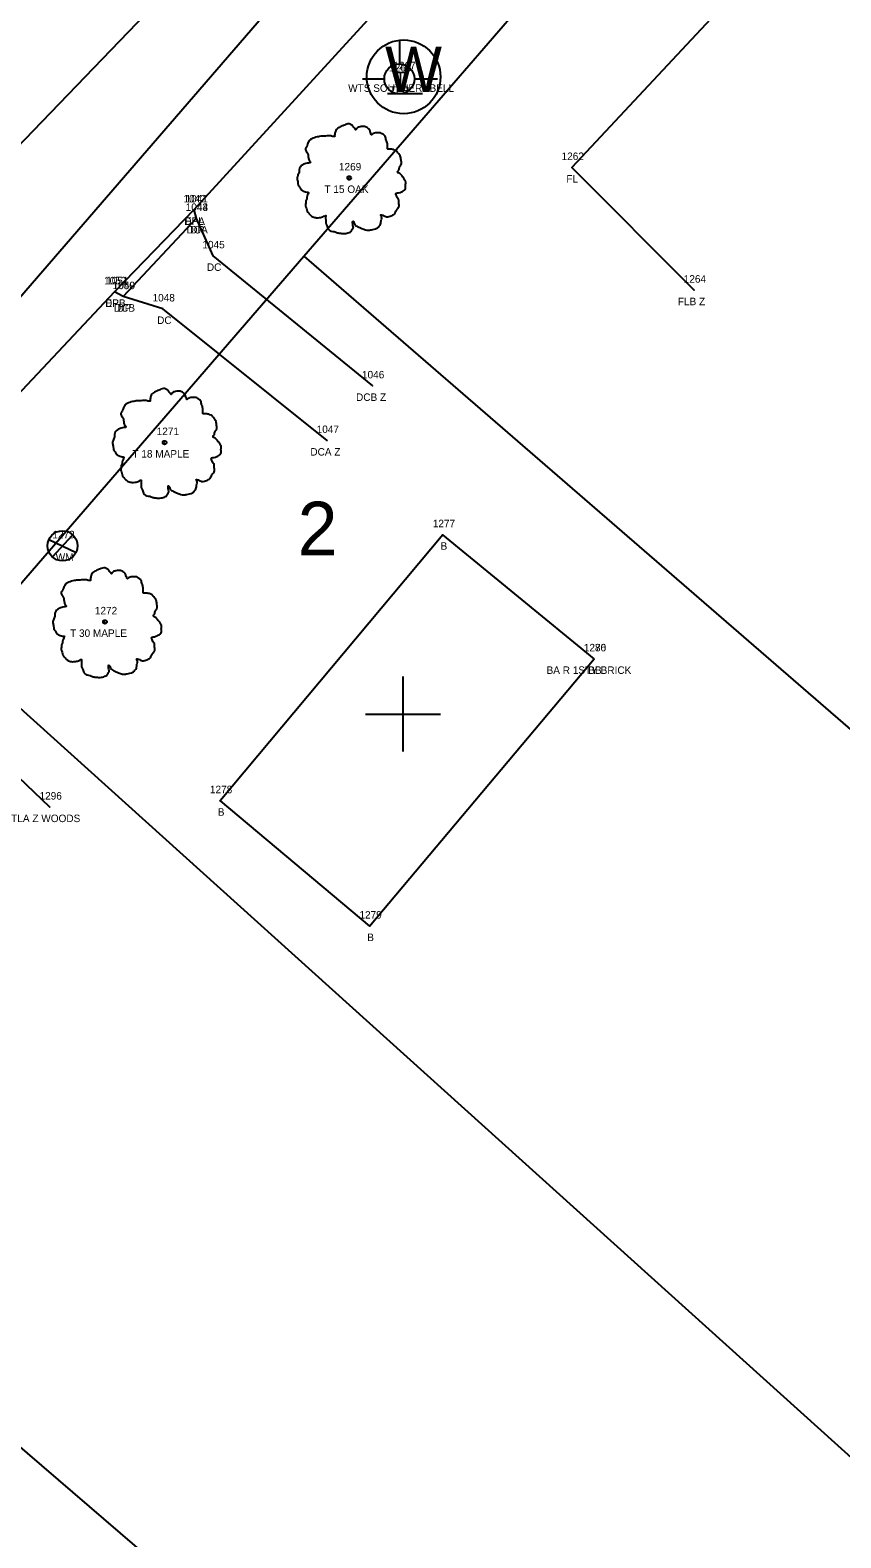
# Model space of a CAD drawing. Extents: x 1812113 to 1819860, y 1177395 to 1181185.
# Drawn here: x 1813877.7 to 1813985.7, y 1178074.8 to 1178275.6 of the extents above; entities that cross this region are included whole.
import ezdxf

# ---------------------------------------------------------------- set-up
doc = ezdxf.new("R2010")
doc.units = 0
for name, color, linetype in [('RD_EX_Bldg', 7, 'Continuous'), ('RD_EX_Bldg_txCode', 7, 'Continuous'), ('RD_EX_Conc', 7, 'Continuous'), ('RD_EX_Conc_txCode', 7, 'Continuous'), ('RD_EX_Driveway', 7, 'Continuous'), ('RD_EX_Driveway_txCode', 7, 'Continuous'), ('RD_EX_DV_Prop', 7, 'Continuous'), ('RD_EX_DV_TX_Prop', 7, 'Continuous'), ('RD_EX_Fence_Other', 7, 'Continuous'), ('RD_EX_Fence_Other_txCode', 7, 'Continuous'), ('RD_EX_Misc', 7, 'Continuous'), ('RD_EX_Road', 7, 'Continuous'), ('RD_EX_Road_txCode', 7, 'Continuous'), ('RD_EX_UT', 7, 'Continuous'), ('RD_EX_UT_txCode', 7, 'Continuous'), ('RD_EX_VEG', 7, 'Continuous'), ('RD_EX_VEG_txCode', 7, 'Continuous'), ('RD_HC_CL', 7, 'Continuous'), ('RD_SMD_Locator', 7, 'Continuous')]:
    doc.layers.add(name, color=color, linetype=linetype)

msp = doc.modelspace()

# ---------------------------------------------------------------- linework, layer by layer
at = {"layer": 'RD_EX_Bldg'}
msp.add_lwpolyline([(1813952.83, 1178191.89), (1813932.67, 1178208.43), (1813902.97, 1178173), (1813922.9, 1178156.3), (1813952.83, 1178191.89)], dxfattribs=at)
at = {"layer": 'RD_EX_Conc'}
for points in [[(1813899.79, 1178250.56), (1813902, 1178245.57), (1813923.3, 1178228.25)], [(1813917.24, 1178220.97), (1813895.37, 1178238.5), (1813890.08, 1178240.14)]]:
    msp.add_lwpolyline(points, dxfattribs=at)
at = {"layer": 'RD_EX_Driveway'}
msp.add_lwpolyline([(1813899.48, 1178251.69), (1813899.79, 1178250.56), (1813890.08, 1178240.14), (1813888.9, 1178240.78)], dxfattribs=at)
at = {"layer": 'RD_EX_DV_Prop'}
for p, q in [((1813914.12, 1178245.52), (1814044.97, 1178396.77)), ((1813868.31, 1178192.56), (1813914.12, 1178245.52)), ((1813914.12, 1178245.52), (1814088.82, 1178094.39)), ((1813868.31, 1178192.56), (1814033.95, 1178043.26)), ((1813819.24, 1178135.84), (1813982.43, 1177995.87))]:
    msp.add_line(p, q, dxfattribs=at)
at = {"layer": 'RD_EX_Fence_Other'}
msp.add_lwpolyline([(1814039.17, 1178321.6), (1814032.91, 1178334.96), (1814018.04, 1178330.3), (1813949.86, 1178257.34), (1813966.14, 1178241)], dxfattribs=at)
at = {"layer": 'RD_EX_Misc'}
for p, q in [((1813927.36, 1178179.54), (1813927.36, 1178189.54)), ((1813922.36, 1178184.54), (1813932.36, 1178184.54))]:
    msp.add_line(p, q, dxfattribs=at)
at = {"layer": 'RD_EX_Road'}
for p, q in [((1813874.69, 1178258.74), (1813910.02, 1178295.38)), ((1813927.09, 1178281.88), (1813899.48, 1178251.69)), ((1813899.48, 1178251.69), (1813888.9, 1178240.78)), ((1813888.9, 1178240.78), (1813846.63, 1178195.79))]:
    msp.add_line(p, q, dxfattribs=at)
at = {"layer": 'RD_EX_UT'}
for p, q in [((1813926.87, 1178274.22), (1813926.87, 1178271.15)), ((1813921.94, 1178269.17), (1813924.87, 1178269.17)), ((1813928.87, 1178269.17), (1813931.94, 1178269.17)), ((1813925.31, 1178267.21), (1813929.94, 1178267.21)), ((1813880.63, 1178205.49), (1813883.29, 1178208.39)), ((1813880.15, 1178207.79), (1813883.78, 1178206.07))]:
    msp.add_line(p, q, dxfattribs=at)
for centre, radius in [((1813927.44, 1178269.42), 4.91), ((1813926.87, 1178269.15), 2), ((1813881.98, 1178206.95), 2)]:
    msp.add_circle(centre, radius, dxfattribs=at)
at = {"layer": 'RD_EX_VEG'}
msp.add_lwpolyline([(1813880.29, 1178172.15), (1813856.42, 1178194.9), (1813848.45, 1178185.53)], dxfattribs=at)
for centre, radius in [((1813920.19, 1178255.95), 0.25), ((1813920.17, 1178255.94), 0.0001), ((1813895.59, 1178220.7), 0.25), ((1813895.58, 1178220.69), 0.0001), ((1813887.64, 1178196.82), 0.25), ((1813887.63, 1178196.81), 0.0001)]:
    msp.add_circle(centre, radius, dxfattribs=at)
for points in [[(1813920.32, 1178263.12), (1813920.02, 1178263.15), (1813919.69, 1178263.05), (1813919.44, 1178262.95), (1813919.22, 1178262.87), (1813918.99, 1178262.77), (1813918.69, 1178262.6), (1813918.47, 1178262.4), (1813918.34, 1178262.15), (1813918.29, 1178261.92), (1813918.24, 1178261.65), (1813918.24, 1178261.47), (1813918.12, 1178261.45), (1813917.97, 1178261.47), (1813917.72, 1178261.55), (1813917.47, 1178261.55), (1813917.22, 1178261.55), (1813916.87, 1178261.52), (1813916.52, 1178261.52), (1813916.25, 1178261.47), (1813915.92, 1178261.42), (1813915.55, 1178261.3), (1813915.2, 1178261.17), (1813914.9, 1178260.92), (1813914.65, 1178260.45), (1813914.52, 1178260.1), (1813914.37, 1178259.85), (1813914.52, 1178259.4), (1813914.7, 1178259.05), (1813914.72, 1178258.85), (1813914.8, 1178258.42), (1813914.9, 1178258.2), (1813915.02, 1178258), (1813914.95, 1178257.97), (1813914.57, 1178257.92), (1813914.27, 1178257.82), (1813913.85, 1178257.6), (1813913.62, 1178257.37), (1813913.52, 1178257.05), (1813913.5, 1178256.7), (1813913.4, 1178256.5), (1813913.32, 1178256.22), (1813913.3, 1178256.15), (1813913.25, 1178255.82), (1813913.35, 1178255.37), (1813913.37, 1178255.02), (1813913.5, 1178254.8), (1813913.65, 1178254.63), (1813913.82, 1178254.38), (1813914.22, 1178254.15), (1813914.55, 1178254.05), (1813914.75, 1178254.03), (1813914.57, 1178253.53), (1813914.52, 1178253.18), (1813914.4, 1178252.78), (1813914.4, 1178252.7), (1813914.35, 1178252.23), (1813914.5, 1178251.9), (1813914.57, 1178251.53), (1813914.75, 1178251.3), (1813915.02, 1178251), (1813915.35, 1178250.78), (1813915.85, 1178250.65), (1813916.25, 1178250.68), (1813916.82, 1178250.85), (1813917.07, 1178250.93), (1813917.04, 1178250.75), (1813917.07, 1178250.38), (1813917.07, 1178249.95), (1813917.22, 1178249.63), (1813917.32, 1178249.35), (1813917.47, 1178249.1), (1813917.79, 1178248.88), (1813918.19, 1178248.8), (1813918.62, 1178248.65), (1813919.07, 1178248.58), (1813919.57, 1178248.55), (1813920.17, 1178248.7), (1813920.44, 1178248.83), (1813920.54, 1178249), (1813920.74, 1178249.38), (1813920.69, 1178249.6), (1813920.72, 1178250.2), (1813920.82, 1178250.03), (1813920.99, 1178249.68), (1813921.49, 1178249.38), (1813921.89, 1178249.2), (1813922.37, 1178249.05), (1813922.67, 1178248.98), (1813923.14, 1178249.05), (1813923.52, 1178249.13), (1813923.89, 1178249.25), (1813924.19, 1178249.53), (1813924.37, 1178249.8), (1813924.42, 1178250.08), (1813924.49, 1178250.45), (1813924.54, 1178250.63)], [(1813924.54, 1178250.63), (1813924.47, 1178250.8), (1813924.42, 1178251.05), (1813924.49, 1178251.03), (1813924.67, 1178250.98), (1813924.94, 1178250.85), (1813925.17, 1178250.78), (1813925.49, 1178250.8), (1813925.77, 1178250.9), (1813926.22, 1178251.18), (1813926.49, 1178251.65), (1813926.77, 1178252.05), (1813926.84, 1178252.38), (1813926.79, 1178252.6), (1813926.77, 1178253.1), (1813926.57, 1178253.35), (1813926.52, 1178253.48), (1813926.42, 1178253.88), (1813926.49, 1178253.93), (1813926.77, 1178253.98), (1813927.14, 1178254.1), (1813927.42, 1178254.23), (1813927.64, 1178254.4), (1813927.71, 1178254.63), (1813927.69, 1178255.02), (1813927.74, 1178255.42), (1813927.67, 1178255.57), (1813927.57, 1178255.72), (1813927.49, 1178255.92), (1813927.34, 1178256.07), (1813927.24, 1178256.22), (1813927.14, 1178256.32), (1813927.02, 1178256.47), (1813926.84, 1178256.6), (1813926.69, 1178256.65), (1813926.64, 1178256.8), (1813926.79, 1178257), (1813926.84, 1178257.1), (1813926.87, 1178257.32), (1813927.09, 1178257.67), (1813927.14, 1178258.07), (1813927.09, 1178258.5), (1813927.04, 1178258.77), (1813926.89, 1178259.05), (1813926.69, 1178259.3), (1813926.57, 1178259.47), (1813926.39, 1178259.6), (1813926.07, 1178259.72), (1813925.82, 1178259.77), (1813925.47, 1178259.77), (1813925.27, 1178259.82), (1813925.29, 1178259.87), (1813925.29, 1178260.02), (1813925.29, 1178260.3), (1813925.22, 1178260.75), (1813925.07, 1178261.25), (1813925.07, 1178261.27), (1813924.97, 1178261.52), (1813924.74, 1178261.72), (1813924.57, 1178261.82), (1813924.37, 1178261.95), (1813924.12, 1178261.97), (1813923.82, 1178261.97), (1813923.54, 1178261.92), (1813923.34, 1178261.82), (1813923.17, 1178261.7), (1813923.09, 1178261.85), (1813922.99, 1178262.15), (1813922.94, 1178262.3), (1813922.79, 1178262.47), (1813922.57, 1178262.67), (1813922.12, 1178262.8), (1813921.49, 1178262.72), (1813921.19, 1178262.52), (1813921.04, 1178262.35), (1813920.99, 1178262.47), (1813920.79, 1178262.67), (1813920.69, 1178262.85), (1813920.52, 1178262.97), (1813920.37, 1178263.07), (1813920.27, 1178263.12)], [(1813895.72, 1178227.87), (1813895.42, 1178227.9), (1813895.1, 1178227.8), (1813894.85, 1178227.7), (1813894.62, 1178227.62), (1813894.4, 1178227.52), (1813894.1, 1178227.35), (1813893.87, 1178227.15), (1813893.75, 1178226.9), (1813893.7, 1178226.67), (1813893.65, 1178226.4), (1813893.65, 1178226.22), (1813893.52, 1178226.2), (1813893.37, 1178226.22), (1813893.12, 1178226.3), (1813892.87, 1178226.3), (1813892.62, 1178226.3), (1813892.27, 1178226.27), (1813891.92, 1178226.27), (1813891.65, 1178226.22), (1813891.32, 1178226.17), (1813890.95, 1178226.05), (1813890.6, 1178225.92), (1813890.3, 1178225.67), (1813890.05, 1178225.2), (1813889.92, 1178224.85), (1813889.77, 1178224.6), (1813889.92, 1178224.15), (1813890.1, 1178223.8), (1813890.12, 1178223.6), (1813890.2, 1178223.17), (1813890.3, 1178222.95), (1813890.42, 1178222.75), (1813890.35, 1178222.72), (1813889.97, 1178222.67), (1813889.67, 1178222.57), (1813889.25, 1178222.35), (1813889.02, 1178222.12), (1813888.92, 1178221.8), (1813888.9, 1178221.45), (1813888.8, 1178221.25), (1813888.72, 1178220.97), (1813888.7, 1178220.9), (1813888.65, 1178220.58), (1813888.75, 1178220.13), (1813888.77, 1178219.78), (1813888.9, 1178219.55), (1813889.05, 1178219.38), (1813889.22, 1178219.13), (1813889.62, 1178218.9), (1813889.95, 1178218.8), (1813890.15, 1178218.78), (1813889.97, 1178218.28), (1813889.92, 1178217.93), (1813889.8, 1178217.53), (1813889.8, 1178217.45), (1813889.75, 1178216.98), (1813889.9, 1178216.65), (1813889.97, 1178216.28), (1813890.15, 1178216.05), (1813890.42, 1178215.75), (1813890.75, 1178215.53), (1813891.25, 1178215.4), (1813891.65, 1178215.43), (1813892.22, 1178215.6), (1813892.47, 1178215.68), (1813892.45, 1178215.5), (1813892.47, 1178215.13), (1813892.47, 1178214.7), (1813892.62, 1178214.38), (1813892.72, 1178214.1), (1813892.87, 1178213.85), (1813893.2, 1178213.63), (1813893.6, 1178213.55), (1813894.02, 1178213.4), (1813894.47, 1178213.33), (1813894.97, 1178213.3), (1813895.57, 1178213.45), (1813895.85, 1178213.58), (1813895.95, 1178213.75), (1813896.15, 1178214.13), (1813896.1, 1178214.35), (1813896.12, 1178214.95), (1813896.22, 1178214.78), (1813896.4, 1178214.43), (1813896.9, 1178214.13), (1813897.29, 1178213.95), (1813897.77, 1178213.8), (1813898.07, 1178213.73), (1813898.54, 1178213.8), (1813898.92, 1178213.88), (1813899.29, 1178214), (1813899.59, 1178214.28), (1813899.77, 1178214.55), (1813899.82, 1178214.83), (1813899.89, 1178215.2), (1813899.94, 1178215.38)], [(1813899.94, 1178215.38), (1813899.87, 1178215.55), (1813899.82, 1178215.8), (1813899.89, 1178215.78), (1813900.07, 1178215.73), (1813900.34, 1178215.6), (1813900.57, 1178215.53), (1813900.89, 1178215.55), (1813901.17, 1178215.65), (1813901.62, 1178215.93), (1813901.89, 1178216.4), (1813902.17, 1178216.8), (1813902.24, 1178217.13), (1813902.19, 1178217.35), (1813902.17, 1178217.85), (1813901.97, 1178218.1), (1813901.92, 1178218.23), (1813901.82, 1178218.63), (1813901.89, 1178218.68), (1813902.17, 1178218.73), (1813902.54, 1178218.85), (1813902.82, 1178218.98), (1813903.04, 1178219.15), (1813903.12, 1178219.38), (1813903.09, 1178219.78), (1813903.14, 1178220.18), (1813903.07, 1178220.33), (1813902.97, 1178220.48), (1813902.89, 1178220.68), (1813902.74, 1178220.82), (1813902.64, 1178220.97), (1813902.54, 1178221.07), (1813902.42, 1178221.22), (1813902.24, 1178221.35), (1813902.09, 1178221.4), (1813902.04, 1178221.55), (1813902.19, 1178221.75), (1813902.24, 1178221.85), (1813902.27, 1178222.07), (1813902.49, 1178222.42), (1813902.54, 1178222.82), (1813902.49, 1178223.25), (1813902.44, 1178223.52), (1813902.29, 1178223.8), (1813902.09, 1178224.05), (1813901.97, 1178224.22), (1813901.79, 1178224.35), (1813901.47, 1178224.47), (1813901.22, 1178224.52), (1813900.87, 1178224.52), (1813900.67, 1178224.57), (1813900.69, 1178224.62), (1813900.69, 1178224.77), (1813900.69, 1178225.05), (1813900.62, 1178225.5), (1813900.47, 1178226), (1813900.47, 1178226.02), (1813900.37, 1178226.27), (1813900.14, 1178226.47), (1813899.97, 1178226.57), (1813899.77, 1178226.7), (1813899.52, 1178226.72), (1813899.22, 1178226.72), (1813898.94, 1178226.67), (1813898.74, 1178226.57), (1813898.57, 1178226.45), (1813898.49, 1178226.6), (1813898.39, 1178226.9), (1813898.34, 1178227.05), (1813898.19, 1178227.22), (1813897.97, 1178227.42), (1813897.52, 1178227.55), (1813896.9, 1178227.47), (1813896.6, 1178227.27), (1813896.45, 1178227.1), (1813896.4, 1178227.22), (1813896.2, 1178227.42), (1813896.1, 1178227.6), (1813895.92, 1178227.72), (1813895.77, 1178227.82), (1813895.67, 1178227.87)], [(1813887.77, 1178203.99), (1813887.47, 1178204.02), (1813887.15, 1178203.92), (1813886.9, 1178203.82), (1813886.67, 1178203.74), (1813886.45, 1178203.64), (1813886.15, 1178203.47), (1813885.92, 1178203.27), (1813885.8, 1178203.02), (1813885.75, 1178202.79), (1813885.7, 1178202.52), (1813885.7, 1178202.34), (1813885.57, 1178202.32), (1813885.42, 1178202.34), (1813885.17, 1178202.42), (1813884.92, 1178202.42), (1813884.67, 1178202.42), (1813884.32, 1178202.39), (1813883.97, 1178202.39), (1813883.7, 1178202.34), (1813883.37, 1178202.29), (1813883, 1178202.17), (1813882.65, 1178202.04), (1813882.35, 1178201.79), (1813882.1, 1178201.32), (1813881.97, 1178200.97), (1813881.82, 1178200.72), (1813881.97, 1178200.27), (1813882.15, 1178199.92), (1813882.17, 1178199.72), (1813882.25, 1178199.29), (1813882.35, 1178199.07), (1813882.47, 1178198.87), (1813882.4, 1178198.84), (1813882.02, 1178198.79), (1813881.72, 1178198.69), (1813881.3, 1178198.47), (1813881.07, 1178198.24), (1813880.97, 1178197.92), (1813880.95, 1178197.57), (1813880.85, 1178197.37), (1813880.77, 1178197.09), (1813880.75, 1178197.02), (1813880.7, 1178196.69), (1813880.8, 1178196.24), (1813880.82, 1178195.89), (1813880.95, 1178195.67), (1813881.1, 1178195.5), (1813881.27, 1178195.25), (1813881.67, 1178195.02), (1813882, 1178194.92), (1813882.2, 1178194.9), (1813882.02, 1178194.4), (1813881.97, 1178194.05), (1813881.85, 1178193.65), (1813881.85, 1178193.57), (1813881.8, 1178193.1), (1813881.95, 1178192.77), (1813882.02, 1178192.4), (1813882.2, 1178192.17), (1813882.47, 1178191.87), (1813882.8, 1178191.65), (1813883.3, 1178191.52), (1813883.7, 1178191.55), (1813884.27, 1178191.72), (1813884.52, 1178191.8), (1813884.5, 1178191.62), (1813884.52, 1178191.25), (1813884.52, 1178190.82), (1813884.67, 1178190.5), (1813884.77, 1178190.22), (1813884.92, 1178189.97), (1813885.25, 1178189.75), (1813885.65, 1178189.67), (1813886.07, 1178189.52), (1813886.52, 1178189.45), (1813887.02, 1178189.42), (1813887.62, 1178189.57), (1813887.9, 1178189.7), (1813888, 1178189.87), (1813888.2, 1178190.25), (1813888.15, 1178190.47), (1813888.17, 1178191.07), (1813888.27, 1178190.9), (1813888.45, 1178190.55), (1813888.95, 1178190.25), (1813889.34, 1178190.07), (1813889.82, 1178189.92), (1813890.12, 1178189.85), (1813890.59, 1178189.92), (1813890.97, 1178190), (1813891.34, 1178190.12), (1813891.64, 1178190.4), (1813891.82, 1178190.67), (1813891.87, 1178190.95), (1813891.94, 1178191.32), (1813891.99, 1178191.5)], [(1813891.99, 1178191.5), (1813891.92, 1178191.67), (1813891.87, 1178191.92), (1813891.94, 1178191.9), (1813892.12, 1178191.85), (1813892.39, 1178191.72), (1813892.62, 1178191.65), (1813892.94, 1178191.67), (1813893.22, 1178191.77), (1813893.67, 1178192.05), (1813893.94, 1178192.52), (1813894.22, 1178192.92), (1813894.29, 1178193.25), (1813894.24, 1178193.47), (1813894.22, 1178193.97), (1813894.02, 1178194.22), (1813893.97, 1178194.35), (1813893.87, 1178194.75), (1813893.94, 1178194.8), (1813894.22, 1178194.85), (1813894.59, 1178194.97), (1813894.87, 1178195.1), (1813895.09, 1178195.27), (1813895.17, 1178195.5), (1813895.14, 1178195.89), (1813895.19, 1178196.29), (1813895.12, 1178196.44), (1813895.02, 1178196.59), (1813894.94, 1178196.79), (1813894.79, 1178196.94), (1813894.69, 1178197.09), (1813894.59, 1178197.19), (1813894.47, 1178197.34), (1813894.29, 1178197.47), (1813894.14, 1178197.52), (1813894.09, 1178197.67), (1813894.24, 1178197.87), (1813894.29, 1178197.97), (1813894.32, 1178198.19), (1813894.54, 1178198.54), (1813894.59, 1178198.94), (1813894.54, 1178199.37), (1813894.49, 1178199.64), (1813894.34, 1178199.92), (1813894.14, 1178200.17), (1813894.02, 1178200.34), (1813893.84, 1178200.47), (1813893.52, 1178200.59), (1813893.27, 1178200.64), (1813892.92, 1178200.64), (1813892.72, 1178200.69), (1813892.74, 1178200.74), (1813892.74, 1178200.89), (1813892.74, 1178201.17), (1813892.67, 1178201.62), (1813892.52, 1178202.12), (1813892.52, 1178202.14), (1813892.42, 1178202.39), (1813892.19, 1178202.59), (1813892.02, 1178202.69), (1813891.82, 1178202.82), (1813891.57, 1178202.84), (1813891.27, 1178202.84), (1813890.99, 1178202.79), (1813890.79, 1178202.69), (1813890.62, 1178202.57), (1813890.54, 1178202.72), (1813890.44, 1178203.02), (1813890.39, 1178203.17), (1813890.24, 1178203.34), (1813890.02, 1178203.54), (1813889.57, 1178203.67), (1813888.95, 1178203.59), (1813888.65, 1178203.39), (1813888.5, 1178203.22), (1813888.45, 1178203.34), (1813888.25, 1178203.54), (1813888.15, 1178203.72), (1813887.97, 1178203.84), (1813887.82, 1178203.94), (1813887.72, 1178203.99)]]:
    msp.add_spline(points, degree=3, dxfattribs=at)
at = {"layer": 'RD_HC_CL'}
msp.add_line((1814048.02, 1178438.51), (1813851.74, 1178211.63), dxfattribs=at)
at = {"layer": 'RD_SMD_Locator'}
for centre in [(1813949.86, 1178257.34), (1813899.48, 1178251.69), (1813899.48, 1178251.69), (1813899.79, 1178250.56), (1813899.79, 1178250.56), (1813902, 1178245.57), (1813888.9, 1178240.78), (1813888.9, 1178240.78), (1813966.14, 1178241), (1813890.08, 1178240.14), (1813890.08, 1178240.14), (1813895.37, 1178238.5), (1813923.3, 1178228.25), (1813917.24, 1178220.97), (1813932.67, 1178208.43), (1813952.83, 1178191.89), (1813952.83, 1178191.89), (1813880.29, 1178172.15), (1813902.97, 1178173), (1813922.9, 1178156.3)]:
    msp.add_circle(centre, 0.001, dxfattribs=at)

# ---------------------------------------------------------------- texts
at = {"layer": 'RD_EX_Bldg_txCode'}
for s, p in [('1277', (1813931.33, 1178209.43)), ('B', (1813932.36, 1178206.43)), ('1280', (1813951.45, 1178192.89)), ('1276', (1813951.46, 1178192.89)), ('BA R 1STY BRICK', (1813946.49, 1178189.89)), ('BB', (1813952.05, 1178189.89)), ('1278', (1813901.63, 1178174)), ('B', (1813902.67, 1178171)), ('1279', (1813921.55, 1178157.3)), ('B', (1813922.59, 1178154.3))]:
    msp.add_text(s, height=1, dxfattribs=at).set_placement(p)
at = {"layer": 'RD_EX_Conc_txCode'}
for s, p in [('1044', (1813898.4, 1178251.56)), ('DCA', (1813898.52, 1178248.56)), ('1045', (1813900.62, 1178246.57)), ('DC', (1813901.22, 1178243.57)), ('1049', (1813888.69, 1178241.14)), ('1048', (1813893.98, 1178239.5)), ('DCB', (1813888.83, 1178238.14)), ('DC', (1813894.59, 1178236.5)), ('1046', (1813921.89, 1178229.25)), ('DCB Z', (1813921.1, 1178226.25)), ('1047', (1813915.85, 1178221.97)), ('DCA Z', (1813915.01, 1178218.97))]:
    msp.add_text(s, height=1, dxfattribs=at).set_placement(p)
at = {"layer": 'RD_EX_Driveway_txCode'}
for s, p in [('1042', (1813898.1, 1178252.69)), ('1043', (1813898.4, 1178251.56)), ('DPA', (1813898.21, 1178249.69)), ('DP', (1813899.01, 1178248.56)), ('1051', (1813887.8, 1178241.78)), ('1050', (1813888.65, 1178241.14)), ('DPB', (1813887.65, 1178238.78)), ('DP', (1813889.3, 1178238.14))]:
    msp.add_text(s, height=1, dxfattribs=at).set_placement(p)
at = {"layer": 'RD_EX_DV_TX_Prop'}
msp.add_text('2', height=7.14, dxfattribs=at).set_placement((1813913.32, 1178205.68))
at = {"layer": 'RD_EX_Fence_Other_txCode'}
for s, p in [('1262', (1813948.49, 1178258.34)), ('FL', (1813949.13, 1178255.34)), ('1264', (1813964.77, 1178242)), ('FLB Z', (1813963.99, 1178239))]:
    msp.add_text(s, height=1, dxfattribs=at).set_placement(p)
at = {"layer": 'RD_EX_Road_txCode'}
for s, p in [('1041', (1813898.38, 1178252.69)), ('EPL', (1813898.28, 1178249.69)), ('1052', (1813887.52, 1178241.78)), ('EPL', (1813887.7, 1178238.78))]:
    msp.add_text(s, height=1, dxfattribs=at).set_placement(p)
at = {"layer": 'RD_EX_UT'}
for s, height, p in [('W', 6, (1813924.97, 1178267.42)), ('T', 2, (1813926.2, 1178268.11))]:
    msp.add_text(s, height=height, dxfattribs=at).set_placement(p)
at = {"layer": 'RD_EX_UT_txCode'}
for s, p in [('1268', (1813925.5, 1178270.15)), ('1267', (1813926.07, 1178270.42)), ('WTS SOUTHERNBELL', (1813920.05, 1178267.42)), ('TPP', (1813925.6, 1178267.15)), ('1273', (1813880.63, 1178207.95)), ('WM', (1813881.07, 1178204.95))]:
    msp.add_text(s, height=1, dxfattribs=at).set_placement(p)
at = {"layer": 'RD_EX_VEG_txCode'}
for s, p in [('1269', (1813918.82, 1178256.95)), ('T 15 OAK', (1813916.89, 1178253.95)), ('1271', (1813894.53, 1178221.7)), ('T 18 MAPLE', (1813891.3, 1178218.7)), ('1272', (1813886.29, 1178197.82)), ('T 30 MAPLE', (1813882.99, 1178194.82)), ('1296', (1813878.92, 1178173.15)), ('TLA Z WOODS', (1813875.14, 1178170.15))]:
    msp.add_text(s, height=1, dxfattribs=at).set_placement(p)

doc.saveas('drawing.dxf')
